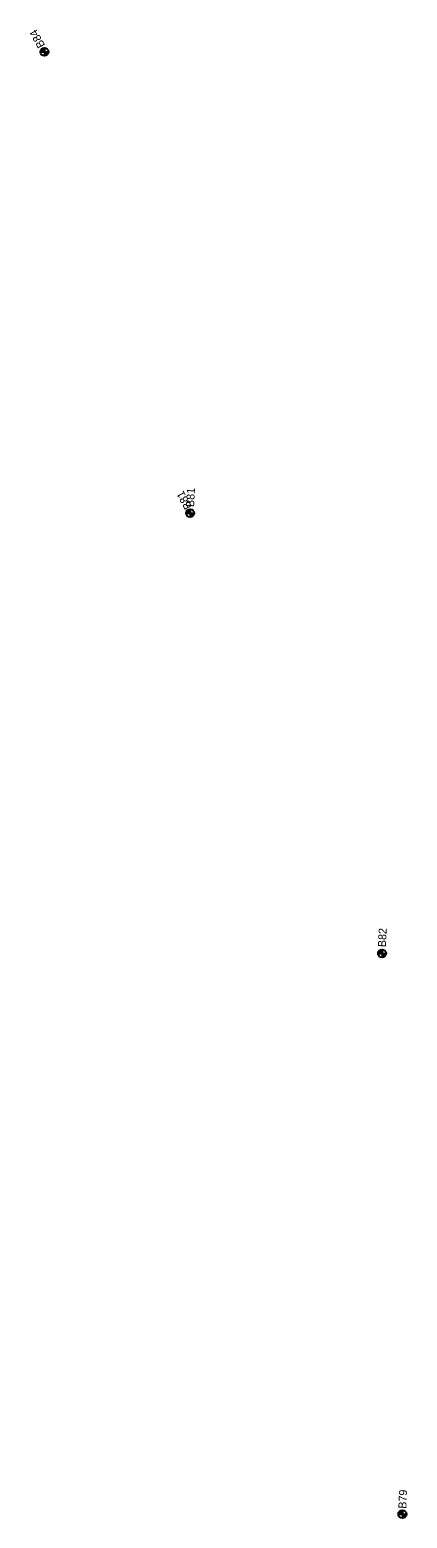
# Model space of a CAD drawing. Extents: x 345549 to 379569, y 127949 to 230467.
# Drawn here: x 359617 to 360089, y 174730 to 176590 of the extents above; entities that cross this region are included whole.
import ezdxf

# ---------------------------------------------------------------- set-up
doc = ezdxf.new("R2010")
doc.units = 0
for name, color, linetype in [('E_SOIL_BORE1 [KAPUR_CADDS_LEVELS]', 7, 'Continuous'), ('E_SOIL_BORE2 [KAPUR_CADDS_LEVELS]', 7, 'Continuous'), ('P_MARK', 7, 'Continuous')]:
    doc.layers.add(name, color=color, linetype=linetype)

msp = doc.modelspace()

# ---------------------------------------------------------------- linework, layer by layer
at = {"layer": 'P_MARK'}
for p, q in [((359635.4, 176567.4), (359635.4, 176557.4)), ((359630.4, 176562.4), (359640.4, 176562.4)), ((359817.5, 175990.9), (359817.5, 175980.9)), ((359812.5, 175985.9), (359822.5, 175985.9)), ((360052.2, 175435.6), (360062.2, 175435.6)), ((360057.2, 175440.6), (360057.2, 175430.6)), ((360077.6, 174734.7), (360087.6, 174734.7)), ((360082.6, 174739.7), (360082.6, 174729.7))]:
    msp.add_line(p, q, dxfattribs=at)
for centre in [(359635.4, 176562.4), (359817.5, 175985.9), (360057.2, 175435.6), (360082.6, 174734.7)]:
    msp.add_circle(centre, 5, dxfattribs=at)
for centre, radius, start, end in [((359635.4, 176562.4), 4.5, 89.9869, 179.9869), ((359635.4, 176562.4), 4, 89.9869, 179.9869), ((359635.4, 176562.4), 3.5, 89.9869, 179.9869), ((359635.4, 176562.4), 3, 89.9869, 179.9869), ((359635.4, 176562.4), 2.5, 89.9869, 179.9869), ((359635.4, 176562.4), 2, 89.9869, 179.9869), ((359635.4, 176562.4), 1.5, 89.9869, 179.9869), ((359635.4, 176562.4), 1, 89.9869, 179.9869), ((359635.4, 176562.4), 0.5, 89.9869, 179.9869), ((359635.4, 176562.4), 4.5, 269.9869, 359.9869), ((359635.4, 176562.4), 4, 269.9869, 359.9869), ((359635.4, 176562.4), 3.5, 269.9869, 359.9869), ((359635.4, 176562.4), 3, 269.9869, 359.9869), ((359635.4, 176562.4), 2.5, 269.9869, 359.9869), ((359635.4, 176562.4), 2, 269.9869, 359.9869), ((359635.4, 176562.4), 1.5, 269.9869, 359.9869), ((359635.4, 176562.4), 1, 269.9869, 359.9869), ((359635.4, 176562.4), 0.5, 269.9869, 359.9869), ((359817.5, 175985.9), 4.5, 89.9869, 179.9869), ((359817.5, 175985.9), 4, 89.9869, 179.9869), ((359817.5, 175985.9), 3.5, 89.9869, 179.9869), ((359817.5, 175985.9), 3, 89.9869, 179.9869), ((359817.5, 175985.9), 2.5, 89.9869, 179.9869), ((359817.5, 175985.9), 2, 89.9869, 179.9869), ((359817.5, 175985.9), 1.5, 89.9869, 179.9869), ((359817.5, 175985.9), 1, 89.9869, 179.9869), ((359817.5, 175985.9), 0.5, 89.9869, 179.9869), ((359817.5, 175985.9), 4.5, 269.9869, 359.9869), ((359817.5, 175985.9), 4, 269.9869, 359.9869), ((359817.5, 175985.9), 3.5, 269.9869, 359.9869), ((359817.5, 175985.9), 3, 269.9869, 359.9869), ((359817.5, 175985.9), 2.5, 269.9869, 359.9869), ((359817.5, 175985.9), 2, 269.9869, 359.9869), ((359817.5, 175985.9), 1.5, 269.9869, 359.9869), ((359817.5, 175985.9), 1, 269.9869, 359.9869), ((359817.5, 175985.9), 0.5, 269.9869, 359.9869), ((360057.2, 175435.6), 4.5, 89.9869, 179.9869), ((360057.2, 175435.6), 4, 89.9869, 179.9869), ((360057.2, 175435.6), 3.5, 89.9869, 179.9869), ((360057.2, 175435.6), 3, 89.9869, 179.9869), ((360057.2, 175435.6), 2.5, 89.9869, 179.9869), ((360057.2, 175435.6), 2, 89.9869, 179.9869), ((360057.2, 175435.6), 1.5, 89.9869, 179.9869), ((360057.2, 175435.6), 1, 89.9869, 179.9869), ((360057.2, 175435.6), 0.5, 89.9869, 179.9869), ((360057.2, 175435.6), 4.5, 269.9869, 359.9869), ((360057.2, 175435.6), 4, 269.9869, 359.9869), ((360057.2, 175435.6), 3.5, 269.9869, 359.9869), ((360057.2, 175435.6), 3, 269.9869, 359.9869), ((360057.2, 175435.6), 2.5, 269.9869, 359.9869), ((360057.2, 175435.6), 2, 269.9869, 359.9869), ((360057.2, 175435.6), 1.5, 269.9869, 359.9869), ((360057.2, 175435.6), 1, 269.9869, 359.9869), ((360057.2, 175435.6), 0.5, 269.9869, 359.9869), ((360082.6, 174734.7), 4.5, 89.9869, 179.9869), ((360082.6, 174734.7), 4, 89.9869, 179.9869), ((360082.6, 174734.7), 3.5, 89.9869, 179.9869), ((360082.6, 174734.7), 3, 89.9869, 179.9869), ((360082.6, 174734.7), 2.5, 89.9869, 179.9869), ((360082.6, 174734.7), 2, 89.9869, 179.9869), ((360082.6, 174734.7), 1.5, 89.9869, 179.9869), ((360082.6, 174734.7), 1, 89.9869, 179.9869), ((360082.6, 174734.7), 0.5, 89.9869, 179.9869), ((360082.6, 174734.7), 4.5, 269.9869, 359.9869), ((360082.6, 174734.7), 4, 269.9869, 359.9869), ((360082.6, 174734.7), 3.5, 269.9869, 359.9869), ((360082.6, 174734.7), 3, 269.9869, 359.9869), ((360082.6, 174734.7), 2.5, 269.9869, 359.9869), ((360082.6, 174734.7), 2, 269.9869, 359.9869), ((360082.6, 174734.7), 1.5, 269.9869, 359.9869), ((360082.6, 174734.7), 1, 269.9869, 359.9869), ((360082.6, 174734.7), 0.5, 269.9869, 359.9869)]:
    msp.add_arc(centre, radius, start, end, dxfattribs=at)

# ---------------------------------------------------------------- texts
at = {"layer": 'E_SOIL_BORE1 [KAPUR_CADDS_LEVELS]'}
for s, p in [('B84', (359636.6, 176570.6)), ('B81', (359820.1, 175993.9))]:
    msp.add_text(s, height=10, rotation=118.6843, dxfattribs=at).set_placement(p)
at = {"layer": 'E_SOIL_BORE2 [KAPUR_CADDS_LEVELS]'}
for s, p in [('B81', (359822.4, 175993.4)), ('B82', (360062, 175443.3)), ('B79', (360087.5, 174741.4))]:
    msp.add_text(s, height=10, rotation=87.2646, dxfattribs=at).set_placement(p)

doc.saveas('drawing.dxf')
